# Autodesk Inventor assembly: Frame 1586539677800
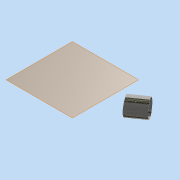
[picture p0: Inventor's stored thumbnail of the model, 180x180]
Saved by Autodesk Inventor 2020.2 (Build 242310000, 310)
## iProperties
Created: 2020-04
Part Number: Frame 1586539677800
Document SubType Name: Assembly
Designer: t.sancier
_FrameDoc: Frame Assembly
_Version: 15.0.0
Author: t.sancier
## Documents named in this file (3)
- F:\inventor\Robustesse maquette numérique\test cuve\Frame\Frame 1586539677800.iam
- F:\inventor\Robustesse maquette numérique\test cuve\Frame\Skeleton 1586539677801.ipt
- F:\inventor\Robustesse maquette numérique\test cuve\Frame\DIN 168,3 x 5 1586539679249.ipt
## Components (2 placed, 2 different names)
1. Modèle de référence de l'ossature
2. DIN 168,3 x 5:1
